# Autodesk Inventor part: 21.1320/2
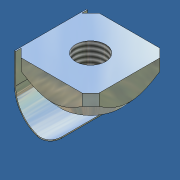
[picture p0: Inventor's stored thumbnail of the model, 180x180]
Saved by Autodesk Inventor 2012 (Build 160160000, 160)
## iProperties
Created: 2006-12
Part Number: 21.1320/2
Document SubType Name: Modeling
Designer: Andy Moles
Material: Steel, Mild
Density: 7.86 g/cm^3
Mass: 5.5784 g
Surface Area: 8.43697 cm^2
Volume: 0.70972 cm^3
Description: M5 Square Nut With Position Fixing
Vendor: S
Author: Andy Moles
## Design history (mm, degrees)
sketch "Sketch2"
  geometry: L1 (-5.086, -6.5)-(5.086, -6.5); L2 (6.5, -5.086)-(6.5, 5.086); L3 (5.086, 6.5)-(-5.086, 6.5); L4 (-6.5, 5.086)-(-6.5, -5.086); L5 (-6.5, 6.5)-(6.5, -6.5); L6 (5.086, 6.5)-(6.5, 5.086); L7 (0, -6.5)-(0, 6.5); L8 (-6.5, 0)-(6.5, 0); L9 (-5.086, 6.5)-(-6.5, 5.086); L10 (-5.086, -6.5)-(-6.5, -5.086); L11 (5.086, -6.5)-(6.5, -5.086); C1 r 2.5 at (0, 0); 2 further points
  constraints: 22 end point, 6 symmetric about line, 4 parallel, 3 midpoint, 2 coincident, 2 perpendicular, 1 centre point, 1 horizontal
  dimensions: "THREAD" = 5 diameter of C1; "d3" = 45 deg angle of L3 L6 (derived); "d4" = 2 distance of L3.start L2.end
extrude "Extrusion1" new body sketch "Sketch2" distance "d5" = 5.5; taper "d6" = 0 deg
workplane "Work Plane1"
sketch "Sketch4"
  geometry: L1 (10.692, 0)-(5.692, 0) reference; L2 (8.192, 0)-(13.192, 0); L3 (16.385, 5.5)-(16.385, 3.5); L4 (13.192, 0)-(16.797, 3.952); L5 (13.192, 0)-(16.385, 0); L6 (16.385, 3.5)-(16.385, 0); L7 (16.797, 3.952)-(16.797, -0.412); L8 (16.797, -0.412)-(13.192, -0.412); L9 (13.192, -0.412)-(13.192, 0); L10 (8.192, 5.5)-(8.192, 0); L11 (16.385, 5.5)-(16.385, 0) reference; L12 (16.385, 3.5)-(17.502, 3.5); L13 (9.192, 5.5)-(16.385, 5.5) reference
  constraints: 20 end point, 6 perpendicular, 1 collinear, 1 midpoint, 1 parallel, 1 point on line
  dimensions: "d10" = 5 distance of L2.start L2.end; "d15" = 2 distance between parallel lines of L12 L13
revolve "Revolution1" sketch "Sketch4" stored, may be unused: angle "d12" = 90 deg
thread "Thread1" dims "d13" = 10, "d14" = 0
sketch "Sketch6"
  geometry: L1 (6.5, 0)-(6.5, 6.006); L2 (6.5, 0)-(6.5, -5); L3 (6.5, 0)-(6.7, 0); L4 (6.7, 0)-(6.7, -5); L5 (0.9, -10.6)-(0.9, -10.8); L6 (6.5, 0)-(6.5, -1.933); L7 (-5.086, 0)-(5.086, 0); A1 r 5.374 centre (1.131, -5.231) between (0.9, -10.6) and (6.5, -5); A2 r 5.574 centre (1.131, -5.231) between (0.9, -10.8) and (6.7, -5); 3 further points
  constraints: 14 end point, 4 point on circle, 3 collinear, 2 centre point, 2 parallel, 2 perpendicular, 1 coincident
  dimensions: "d21" = 5 distance of L1.start L2.end; "d22" = 0.2 distance of L1.start L3.end; "d23" = 0.2 distance of L5.start L5.end; "d24" = 10.8 distance from line of L5.end L3; "d25" = 5.37434 radius of A1
extrude "Extrusion3" join sketch "Sketch6" stored distance "d26" = 12; taper "d27" = 0 deg
fillet "Fillet2" dims "d28" = 2
fillet "Fillet3" dims "d29" = 2
body "Solid1"
